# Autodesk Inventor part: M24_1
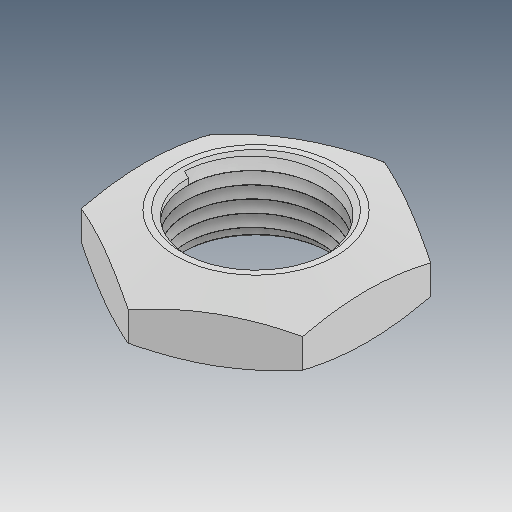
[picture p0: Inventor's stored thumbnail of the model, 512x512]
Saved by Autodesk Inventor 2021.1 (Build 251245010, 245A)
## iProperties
Created: 2019-05
Part Number: M24_1
Material: Ogólny
Document SubType Name: Modeling
Designer: user
Density: 1 g/cm^3
Appearance: Domyślna
Author: user
Revision Number: ÈÎºÎ
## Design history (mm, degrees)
feature "ÊäÈë1"
node "Bryła1"
